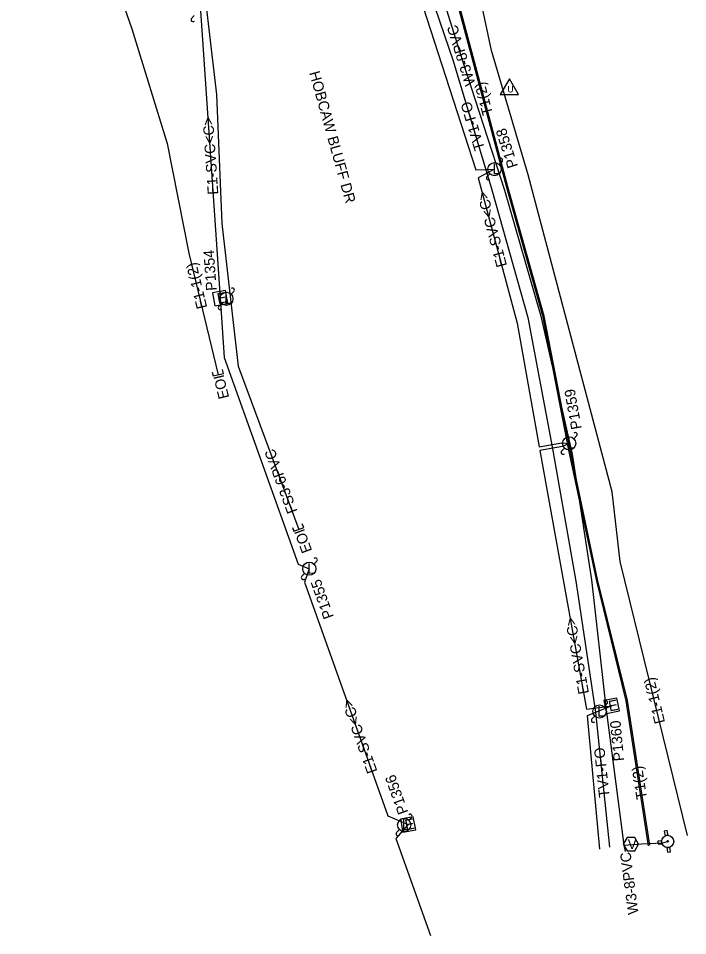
# Model space of a CAD drawing. Extents: x 2336688 to 2352634, y 362473 to 369571.
# Drawn here: x 2347932.5 to 2348185.8, y 366953 to 367300.5 of the extents above; entities that cross this region are included whole.
import ezdxf

# ---------------------------------------------------------------- set-up
doc = ezdxf.new("R2010")
doc.units = 0
for name, color, linetype in [('RD_EX_DV_Prop', 7, 'Continuous'), ('RD_EX_DV_TX_Prop', 7, 'Continuous'), ('RD_EX_RW', 7, 'Continuous'), ('RD_EX_RW_TX', 7, 'Continuous'), ('RD_HC_Data_Tic', 7, 'Continuous'), ('RD_PD_CstnLmt', 7, 'Continuous'), ('RD_PD_Final_TrvlWay', 7, 'Continuous'), ('RD_PD_PatLn3', 7, 'Continuous'), ('RD_Sketch1', 7, 'Continuous'), ('RD_Sketch2', 7, 'Continuous'), ('RD_Sketch5', 7, 'Continuous'), ('RD_TX_Misc1', 7, 'Continuous')]:
    doc.layers.add(name, color=color, linetype=linetype)

msp = doc.modelspace()

# ---------------------------------------------------------------- linework, layer by layer
at = {"layer": 'RD_EX_RW_TX'}
for points in [[(2348088.83, 367494.16), (2348091.17, 367484.78), (2348090.64, 367477.91), (2348089.01, 367470.2), (2348081.09, 367461.1), (2348078.33, 367457.81), (2348071.94, 367420.99), (2348080.69, 367382.96), (2348091.47, 367332.8), (2348104.03, 367285.99), (2348117.2, 367236.51), (2348130.94, 367187.87), (2348140.57, 367137.57), (2348151.22, 367087.99), (2348162.48, 367041.93), (2348170.87, 366987.09)], [(2348171.52, 366987.34), (2348163.05, 367042.11), (2348151.67, 367087.97), (2348141.26, 367137.73), (2348131.53, 367187.73), (2348117.77, 367236.66), (2348104.66, 367285.95), (2348091.99, 367333.07), (2348081.16, 367383.42), (2348072.54, 367421.09), (2348078.97, 367457.45), (2348082.71, 367459.94), (2348088.78, 367458.12), (2348108.47, 367461.17), (2348120.71, 367463.68), (2348126.54, 367465.18), (2348128.12, 367464.52), (2348128.75, 367464.11), (2348130.27, 367463.44), (2348136.63, 367454.72), (2348137.56, 367441.82), (2348146.14, 367387.35)], [(2348085.42, 367455.46), (2348081.41, 367453.31), (2348079.48, 367452.55), (2348059.25, 367433.73), (2348058.03, 367417.18), (2348065.76, 367378.12), (2348081.58, 367329.95), (2348097.08, 367284.38), (2348111.65, 367235.56), (2348125.36, 367187.13), (2348134.58, 367138.22), (2348143.49, 367087.34), (2348150.94, 367037.73), (2348156.27, 366986.52)]]:
    msp.add_lwpolyline(points, dxfattribs=at)
at = {"layer": 'RD_HC_Data_Tic'}
for p, q in [((2347998.05, 367300.49), (2347999.1, 367301.56)), ((2348114.5, 367245.14), (2348115.56, 367246.2)), ((2348109.91, 367240.55), (2348110.97, 367241.61)), ((2348012.99, 367196), (2348014.06, 367197.06)), ((2348008.4, 367191.4), (2348009.46, 367192.46)), ((2348142.76, 367141.25), (2348143.82, 367142.31)), ((2348138.17, 367136.65), (2348139.23, 367137.71)), ((2348044.39, 367093.79), (2348045.45, 367094.85)), ((2348039.79, 367089.19), (2348040.85, 367090.25)), ((2348154.22, 367039.72), (2348155.28, 367040.78)), ((2348149.62, 367035.13), (2348150.69, 367036.19)), ((2348080.27, 366996.73), (2348081.33, 366997.79)), ((2348075.68, 366992.13), (2348076.74, 366993.19))]:
    msp.add_line(p, q, dxfattribs=at)
for centre in [(2348112.74, 367243.38), (2348011.23, 367194.23), (2348141, 367139.48), (2348042.62, 367092.02), (2348152.45, 367037.96), (2348078.51, 366994.96)]:
    msp.add_circle(centre, 2.5, dxfattribs=at)
for centre, start, end in [((2347998.58, 367299.96), 135.5955, 315.5955), ((2348115.03, 367246.73), 315, 135), ((2348110.44, 367240.02), 135, 315), ((2348013.53, 367197.59), 315, 135), ((2348008.93, 367190.87), 135, 315), ((2348143.29, 367142.84), 315, 135), ((2348138.7, 367136.12), 135, 315), ((2348044.92, 367095.38), 315, 135), ((2348040.32, 367088.66), 135, 315), ((2348154.75, 367041.31), 315, 135), ((2348150.15, 367034.6), 135, 315), ((2348080.8, 366998.32), 315, 135), ((2348076.21, 366991.6), 135, 315)]:
    msp.add_arc(centre, 0.75, start, end, dxfattribs=at)
at = {"layer": 'RD_PD_Final_TrvlWay'}
for points in [[(2348085.42, 367455.46), (2348064.82, 367447.53), (2348049.72, 367436.2), (2348053.15, 367416.84), (2348059.59, 367389.88), (2348071.96, 367347.56), (2348081.41, 367349.06), (2348072.77, 367345.05), (2348105.67, 367243.13), (2348112.74, 367243.38), (2348106.57, 367240.06), (2348121.26, 367184.97), (2348129.69, 367138.16), (2348138.15, 367139.68), (2348141, 367139.48), (2348138.4, 367138.3), (2348129.94, 367136.78), (2348147.57, 367038.81), (2348157.07, 367040.12), (2348147.81, 367036.25), (2348152.52, 366985.83)], [(2348185.82, 366991), (2348160.25, 367094.75), (2348157.29, 367121.19), (2348125.49, 367241.23), (2348111.63, 367288.28), (2348101.51, 367335.92), (2348087.12, 367433.5), (2348085.81, 367453.83), (2348085.42, 367455.46)], [(2347932.97, 367422.33), (2347936.06, 367421.7), (2347972.44, 367428.9), (2348001.42, 367303.39), (2348008.91, 367194.49), (2348010.46, 367172.01), (2348038.36, 367093.75), (2348042.62, 367092.02), (2348040.79, 367086.93), (2348072.37, 366998.38), (2348080, 366995.12), (2348075.41, 366989.83), (2348088.54, 366953.03)], [(2347932.97, 367422.33), (2347932.51, 367419.85), (2347936.17, 367410.01), (2347940.24, 367396.21), (2347960.13, 367340.28), (2347975.51, 367296.47), (2347988.87, 367253.06), (2347996.98, 367211.5), (2348008.18, 367165.5)], [(2348005.88, 367166.48), (2348006.23, 367165.03), (2348010.12, 367165.97), (2348009.76, 367167.43)]]:
    msp.add_lwpolyline(points, dxfattribs=at)
for points in [[(2348010.9, 367197.4), (2348005.99, 367196.48), (2348006.91, 367191.57), (2348011.83, 367192.49)], [(2348159.06, 367043.04), (2348154.15, 367042.12), (2348155.07, 367037.2), (2348159.99, 367038.13)], [(2348081.99, 366998.04), (2348077.08, 366997.12), (2348078, 366992.2), (2348082.91, 366993.13)]]:
    msp.add_lwpolyline(points, close=True, dxfattribs=at)
at = {"layer": 'RD_PD_PatLn3'}
msp.add_lwpolyline([(2348118.38, 367277.62), (2348114.92, 367271.62), (2348121.84, 367271.62)], close=True, dxfattribs=at)
at = {"layer": 'RD_Sketch2'}
for p, q in [((2348178.12, 366992.82), (2348176.98, 366992.64)), ((2348176.98, 366992.64), (2348177.27, 366990.8)), ((2348178.4, 366991.02), (2348178.12, 366992.82)), ((2348175.97, 366989), (2348174.49, 366988.77)), ((2348174.49, 366988.77), (2348174.66, 366987.63)), ((2348174.66, 366987.63), (2348176.12, 366987.85)), ((2348177.94, 366986.43), (2348178.22, 366984.65)), ((2348179.36, 366984.83), (2348179.09, 366986.56)), ((2348178.22, 366984.65), (2348179.36, 366984.83))]:
    msp.add_line(p, q, dxfattribs=at)
for points in [[(2348033.84, 367567.03), (2348048.77, 367482.38), (2348049.97, 367475.89), (2348055.35, 367445.23), (2348062.4, 367417.46), (2348070.65, 367378.07), (2348085.84, 367331.58), (2348100.63, 367284.45), (2348116.51, 367235.46), (2348130.22, 367187.62), (2348142.11, 367135.45), (2348149.47, 367087.77), (2348154.82, 367039.58), (2348161.67, 366987.27), (2348162.16, 366984.87)], [(2348161.67, 366987.27), (2348168.3, 366987.86), (2348176.44, 366988.17), (2348178.26, 366988.72)]]:
    msp.add_lwpolyline(points, dxfattribs=at)
msp.add_lwpolyline([(2348167.24, 366987.69), (2348165.79, 366990.19), (2348162.91, 366990.19), (2348161.46, 366987.69), (2348162.91, 366985.19), (2348165.79, 366985.19)], close=True, dxfattribs=at)
for radius in [2.31, 0.289]:
    msp.add_circle((2348178.26, 366988.72), radius, dxfattribs=at)
for start, end in [(173.0411, 202.0084), (86.4806, 115.4569), (262.1343, 291.1106)]:
    msp.add_arc((2348178.26, 366988.72), 2.31, start, end, dxfattribs=at)
at = {"layer": 'RD_Sketch5'}
for points in [[(2347952.57, 367563.69), (2347952.6, 367563.53), (2347954.79, 367551.06), (2347962.49, 367508.35), (2347969.55, 367468.84), (2347978.45, 367425.53), (2347993.78, 367361.64), (2348002.84, 367311.48), (2348007.49, 367271.6), (2348009.48, 367222.84), (2348015.7, 367168.77), (2348038.63, 367106.93)], [(2348036.23, 367107.64), (2348036.75, 367106.23), (2348040.5, 367107.62), (2348039.98, 367109.03)]]:
    msp.add_lwpolyline(points, dxfattribs=at)

# ---------------------------------------------------------------- texts
at = {"layer": 'RD_EX_DV_Prop'}
for s, rotation, p in [('E1-SVC<C>', 93.9349, (2348008.21, 367233.85)), ('E1-SVC<C>', 104.932, (2348117.49, 367206.86)), ('E1-1(2)', 103.6791, (2348004.03, 367190.98)), ('E1-SVC<C>', 100.2056, (2348148.51, 367044.88)), ('E1-1(2)', 103.8455, (2348177.32, 367033.86)), ('E1-SVC<C>', 109.625, (2348068.45, 367015.33))]:
    msp.add_text(s, height=4, rotation=rotation, dxfattribs=at).set_placement(p)
at = {"layer": 'RD_EX_DV_TX_Prop'}
for s, rotation, p in [('P1358', 107.889, (2348121.66, 367244.52)), ('P1354', 93.9349, (2348007.57, 367197.44)), ('P1359', 100.2056, (2348145.77, 367145.14)), ('P1355', 109.625, (2348051.98, 367073.83)), ('P1360', 95.3291, (2348161.82, 367019.29)), ('P1356', 109.625, (2348080.16, 366999.81))]:
    msp.add_text(s, height=4, rotation=rotation, dxfattribs=at).set_placement(p)
at = {"layer": 'RD_EX_RW'}
for s, rotation, p in [('T1(2)', 104.9018, (2348112.18, 367264.36)), ('TV1-FO', 106.6153, (2348109.09, 367251.11)), ('TV1-FO', 95.9495, (2348156.3, 367005.56)), ('T1(2)', 98.7031, (2348170.5, 367004.93))]:
    msp.add_text(s, height=4, rotation=rotation, dxfattribs=at).set_placement(p)
at = {"layer": 'RD_HC_Data_Tic'}
for p in [(2348111.92, 367241.44), (2348010.42, 367192.3), (2348140.19, 367137.55), (2348041.81, 367090.09), (2348151.64, 367036.02), (2348077.7, 366993.03)]:
    msp.add_text('L', height=4, rotation=360, dxfattribs=at).set_placement(p)
at = {"layer": 'RD_PD_CstnLmt'}
for rotation, p in [(107.4281, (2348105.57, 367275.69)), (97.4505, (2348167.26, 366961.33))]:
    msp.add_text('W3-8PVC', height=4, rotation=rotation, dxfattribs=at).set_placement(p)
at = {"layer": 'RD_PD_Final_TrvlWay'}
for s, rotation, p in [('E', 10.6261, (2348008.09, 367192.3)), ('EOI', 103.6791, (2348012.33, 367156.87)), ('E', 10.6261, (2348156.24, 367037.93)), ('E', 10.6261, (2348079.17, 366992.93))]:
    msp.add_text(s, height=4, rotation=rotation, dxfattribs=at).set_placement(p)
at = {"layer": 'RD_PD_PatLn3'}
msp.add_text('U', height=2.4, dxfattribs=at).set_placement((2348117.62, 367272.42))
at = {"layer": 'RD_Sketch1'}
msp.add_text('FS3-6PVC', height=4, rotation=110.3381, dxfattribs=at).set_placement((2348038.21, 367113.82))
at = {"layer": 'RD_Sketch2'}
msp.add_text('V', height=3.75, dxfattribs=at).set_placement((2348163.14, 366985.81))
at = {"layer": 'RD_Sketch5'}
msp.add_text('EOI', height=4, rotation=110.3381, dxfattribs=at).set_placement((2348043.76, 367098.84))
at = {"layer": 'RD_TX_Misc1'}
msp.add_text('HOBCAW BLUFF DR', height=4, rotation=285.5754, dxfattribs=at).set_placement((2348042.56, 367279.88))

doc.saveas('drawing.dxf')
